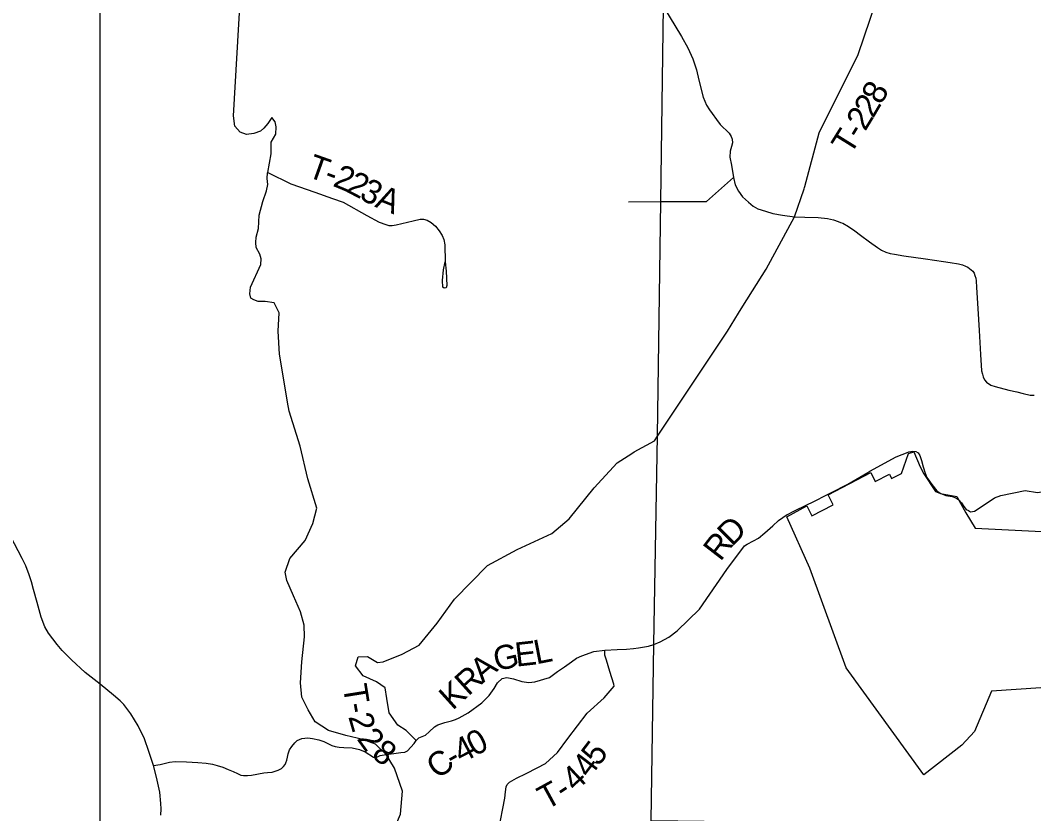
# Model space of a CAD drawing. Extents: x 2402298 to 2498138, y 789485 to 950881.
# Drawn here: x 2447192 to 2459820, y 871864 to 881754 of the extents above; entities that cross this region are included whole.
import ezdxf

# ---------------------------------------------------------------- set-up
doc = ezdxf.new("R2010")
doc.units = 0
for name, color, linetype in [('GM_X_Corporation', 7, 'Continuous'), ('GM_X_County_Road', 7, 'Continuous'), ('GM_X_County_Road_Text', 7, 'Continuous'), ('GM_X_State_Route', 7, 'Continuous'), ('GM_X_Township', 7, 'Continuous'), ('GM_X_Township_Road', 7, 'Continuous'), ('GM_X_Township_Road_Text', 7, 'Continuous'), ('SH_Text', 7, 'Continuous')]:
    doc.layers.add(name, color=color, linetype=linetype)

msp = doc.modelspace()

# ---------------------------------------------------------------- linework, layer by layer
at = {"layer": 'GM_X_Corporation'}
msp.add_lwpolyline([(2459910, 873433), (2459295, 873391), (2459082, 872888), (2458923, 872718), (2458450, 872349), (2457481, 873684), (2457030, 874924), (2456744, 875567), (2456993, 875700), (2457053, 875577), (2457321, 875713), (2457258, 875841), (2457789, 876118), (2457844, 876007), (2458022, 876097), (2458049, 876042), (2458172, 876104), (2458258, 876353), (2458325, 876376), (2458405, 876188), (2458451, 876100), (2458595, 875879), (2458657, 875856), (2458863, 875820), (2458972, 875616), (2459092, 875424), (2460004, 875376)], dxfattribs=at)
at = {"layer": 'GM_X_County_Road'}
for points in [[(2459300, 875783), (2459330, 875803), (2459408, 875832), (2459714, 875892), (2459866, 875867), (2460079, 875905), (2460148, 875978), (2460193, 876060), (2460432, 876476), (2460593, 876723), (2460629, 876769), (2460667, 876804), (2460721, 876846), (2460769, 876871)], [(2458257, 876372), (2458262, 876374), (2458312, 876385), (2458350, 876380), (2458379, 876363), (2458401, 876328), (2458421, 876267), (2458442, 876189), (2458467, 876110), (2458489, 876057), (2458522, 876010)], [(2457753, 876119), (2457779, 876135), (2458106, 876311), (2458257, 876372)], [(2457301, 875869), (2457504, 875972), (2457753, 876119)], [(2458522, 876010), (2458531, 875998), (2458566, 875948), (2458614, 875891), (2458661, 875855), (2458725, 875831), (2458804, 875819), (2458850, 875803), (2458885, 875778), (2458920, 875740), (2458948, 875695), (2458980, 875658), (2459005, 875642), (2459034, 875629), (2459082, 875637), (2459300, 875783)], [(2456750, 875595), (2456831, 875635), (2456994, 875714), (2457072, 875753)], [(2457072, 875753), (2457250, 875843), (2457301, 875869)], [(2454831, 873922), (2454894, 873932), (2455020, 873955), (2455088, 873975), (2455166, 874007), (2455273, 874066), (2455376, 874145), (2455656, 874415), (2455995, 874910), (2456216, 875202), (2456248, 875225), (2456330, 875264), (2456392, 875300), (2456468, 875364), (2456571, 875451), (2456641, 875518), (2456746, 875593), (2456750, 875595)], [(2448850, 872464), (2448935, 872480), (2449052, 872508), (2449121, 872514), (2449262, 872512), (2449404, 872502), (2449510, 872493), (2449589, 872481), (2449647, 872467), (2449717, 872445), (2449781, 872417), (2449843, 872389), (2449899, 872364), (2449942, 872346), (2449972, 872342), (2450024, 872339), (2450072, 872346), (2450228, 872374), (2450274, 872379), (2450331, 872384), (2450369, 872394), (2450407, 872408), (2450446, 872429), (2450473, 872453), (2450491, 872478), (2450500, 872500), (2450514, 872534), (2450522, 872569), (2450530, 872610), (2450547, 872663), (2450574, 872704), (2450614, 872747), (2450643, 872777), (2450701, 872804), (2450775, 872810), (2450835, 872802), (2450913, 872784), (2450976, 872763), (2451040, 872733), (2451075, 872713), (2451115, 872701), (2451166, 872694), (2451225, 872689), (2451329, 872687), (2451417, 872667), (2451490, 872638), (2451592, 872571), (2451627, 872566), (2451677, 872589), (2451751, 872603), (2451846, 872616), (2451933, 872626), (2451982, 872633), (2452017, 872649), (2452098, 872738), (2452126, 872778), (2452157, 872811), (2452243, 872845), (2452286, 872884), (2452355, 872946), (2452394, 872972), (2452480, 873002), (2452565, 873024), (2452613, 873039), (2452662, 873060), (2452771, 873123), (2452945, 873245), (2453034, 873339), (2453097, 873424), (2453137, 873497), (2453197, 873549), (2453255, 873563), (2453338, 873544), (2453443, 873512), (2453529, 873500), (2453602, 873507), (2453787, 873562), (2453885, 873636), (2453972, 873694), (2454061, 873758), (2454122, 873802), (2454187, 873833), (2454339, 873886), (2454474, 873903), (2454629, 873910), (2454744, 873917), (2454831, 873922)]]:
    msp.add_lwpolyline(points, dxfattribs=at)
at = {"layer": 'GM_X_State_Route'}
for points in [[(2455208, 881922), (2455429, 881553), (2455511, 881409), (2455574, 881273), (2455619, 881136), (2455645, 881007), (2455701, 880795), (2455744, 880695), (2455780, 880637), (2455811, 880592), (2455866, 880516), (2455914, 880453), (2456025, 880347), (2456050, 880306), (2456063, 880270), (2456065, 880228), (2456053, 880181), (2456036, 880121), (2456032, 880046), (2456053, 879946), (2456078, 879794), (2456100, 879702), (2456140, 879623), (2456191, 879555), (2456265, 879487), (2456324, 879438), (2456380, 879403), (2456476, 879373), (2456570, 879347), (2456689, 879324), (2456841, 879305), (2456969, 879301), (2457134, 879294), (2457252, 879282), (2457323, 879266), (2457382, 879247), (2457413, 879234)], [(2457413, 879234), (2457440, 879224), (2457513, 879183), (2457589, 879131), (2457662, 879076), (2457775, 878993), (2457872, 878922), (2457923, 878888), (2457977, 878864), (2458029, 878847), (2458084, 878837), (2458201, 878819), (2458471, 878779), (2458697, 878747), (2458780, 878736), (2458883, 878717), (2458933, 878704), (2458969, 878690), (2458997, 878676), (2459021, 878660), (2459039, 878645), (2459059, 878625), (2459076, 878601), (2459087, 878574), (2459098, 878539), (2459102, 878506), (2459108, 878423), (2459122, 878160), (2459139, 877889), (2459158, 877590), (2459170, 877386), (2459180, 877343), (2459191, 877308), (2459207, 877273), (2459233, 877242), (2459285, 877208), (2459338, 877188), (2459509, 877145), (2459611, 877122), (2459690, 877104), (2459775, 877080), (2459825, 877080)], [(2448850, 872464), (2448794, 872642), (2448738, 872797), (2448659, 872961), (2448571, 873108), (2448481, 873227), (2448435, 873272), (2448355, 873343), (2448187, 873479), (2447999, 873626), (2447832, 873783), (2447712, 873901), (2447650, 873975), (2447597, 874043), (2447545, 874113), (2447499, 874193), (2447452, 874313), (2447402, 874498), (2447358, 874661), (2447332, 874753), (2447303, 874840), (2447263, 874953), (2447215, 875045), (2447071, 875324)], [(2448942, 871847), (2448946, 871925), (2448943, 871990), (2448930, 872133), (2448888, 872322), (2448850, 872464)]]:
    msp.add_lwpolyline(points, dxfattribs=at)
at = {"layer": 'GM_X_Township'}
msp.add_lwpolyline([(2460401, 871709), (2459688, 871718), (2455055, 871774), (2455087, 873978), (2455132, 876575), (2455173, 879496), (2455207, 881924), (2455264, 885930), (2455318, 889770), (2455396, 895324), (2455493, 902184), (2455511, 903524), (2455798, 903521), (2455910, 903520), (2460796, 903505)], dxfattribs=at)
at = {"layer": 'GM_X_Township_Road'}
for points in [[(2456969, 879683), (2457147, 880350), (2457633, 881329), (2458235, 883104), (2458282, 883194)], [(2450274, 879851), (2450275, 879857), (2450297, 879973), (2450320, 880088), (2450317, 880236), (2450375, 880333), (2450381, 880425), (2450369, 880489), (2450326, 880544), (2450278, 880469), (2450227, 880408), (2450186, 880371), (2450100, 880341), (2450010, 880331), (2449930, 880359), (2449864, 880434), (2449849, 880564), (2449938, 882067), (2449934, 882475), (2449941, 882537), (2449977, 882593), (2450053, 882672), (2450207, 882812)], [(2450523, 876996), (2450502, 877123), (2450423, 877592), (2450405, 877878), (2450417, 878109), (2450356, 878231), (2450242, 878247), (2450155, 878247), (2450102, 878269), (2450064, 878290), (2450051, 878346), (2450061, 878429), (2450191, 878711), (2450193, 878780), (2450175, 878838), (2450131, 878922), (2450129, 878985), (2450132, 879049), (2450160, 879158), (2450165, 879240), (2450168, 879326), (2450216, 879494), (2450259, 879628), (2450275, 879707), (2450267, 879783), (2450274, 879851)], [(2450275, 879857), (2450562, 879717), (2450864, 879610), (2451082, 879532), (2451214, 879486), (2451511, 879321), (2451664, 879237), (2451747, 879209), (2451784, 879198), (2451824, 879198), (2451875, 879206), (2451947, 879223), (2452088, 879255), (2452173, 879273), (2452215, 879275), (2452262, 879263), (2452313, 879233), (2452366, 879187), (2452412, 879128), (2452450, 879071), (2452468, 879021), (2452484, 878955), (2452488, 878742), (2452497, 878627), (2452508, 878448), (2452499, 878419), (2452473, 878413), (2452459, 878426), (2452453, 878510), (2452464, 878642), (2452488, 878742)], [(2455208, 879494), (2455743, 879494), (2456078, 879794)], [(2456841, 879305), (2456960, 879655), (2456965, 879668), (2456969, 879683)], [(2454769, 879493), (2455174, 879494), (2455197, 879494), (2455208, 879494)], [(2456141, 878103), (2456197, 878192), (2456484, 878653), (2456841, 879305)], [(2454812, 876356), (2454840, 876374), (2455093, 876511), (2455133, 876572), (2456003, 877881), (2456141, 878103)], [(2451751, 872603), (2451619, 872731), (2451461, 872788), (2451248, 872839), (2451032, 872903), (2450868, 873011), (2450779, 873160), (2450701, 873316), (2450685, 873498), (2450700, 873759), (2450733, 874070), (2450728, 874216), (2450684, 874381), (2450598, 874582), (2450514, 874772), (2450494, 874876), (2450552, 875045), (2450743, 875272), (2450837, 875480), (2450889, 875672), (2450775, 876038), (2450680, 876444), (2450543, 876884), (2450523, 876996)], [(2451759, 873302), (2451740, 873432), (2451631, 873507), (2451464, 873585), (2451370, 873706), (2451401, 873818), (2451517, 873824), (2451644, 873751), (2451712, 873756), (2451951, 873853), (2452164, 873965), (2452387, 874238), (2452604, 874537), (2453014, 874958), (2453384, 875158), (2453814, 875359), (2454032, 875542), (2454342, 875928), (2454631, 876240), (2454812, 876356)], [(2453069, 871307), (2453049, 871410), (2453054, 871450), (2453151, 871650), (2453230, 872058), (2453239, 872138), (2453245, 872198), (2453260, 872228), (2453289, 872257), (2453377, 872307), (2453496, 872366), (2453631, 872437), (2453738, 872491), (2453885, 872628), (2454013, 872804), (2454255, 873117), (2454466, 873308), (2454594, 873454), (2454586, 873481), (2454537, 873636), (2454495, 873779), (2454475, 873841), (2454474, 873903)], [(2452126, 872778), (2452002, 872902), (2451897, 872967), (2451790, 873121), (2451759, 873302)], [(2452305, 869383), (2452306, 869405), (2452313, 869536), (2451886, 869803), (2451810, 870076), (2451806, 870242), (2451770, 870525), (2451544, 870697), (2451337, 870909), (2451316, 871078), (2451457, 871228), (2451565, 871305), (2451636, 871356), (2451825, 871614), (2451930, 871861), (2451953, 872146), (2451855, 872432), (2451751, 872603)]]:
    msp.add_lwpolyline(points, dxfattribs=at)
at = {"layer": 'SH_Text'}
msp.add_lwpolyline([(2448187, 889729), (2496836, 889729), (2496836, 859271), (2448187, 859271)], close=True, dxfattribs=at)

# ---------------------------------------------------------------- texts
at = {"layer": 'GM_X_County_Road_Text'}
for s, rotation, p in [('D', 44.9794, (2456060, 875187)), ('R', 52.3362, (2455916, 875000)), ('E', 6.4377, (2453372, 873697)), ('L', 10.9737, (2453621, 873726)), ('G', 12.8797, (2453124, 873639)), ('A', 40.1232, (2452955, 873486)), ('R', 41.9739, (2452774, 873323)), ('K', 41.9823, (2452578, 873146)), ('0', 27.8832, (2452852, 872574)), ('4', 27.752, (2452688, 872488)), ('C', 36.9035, (2452394, 872286)), ('-', 29.3799, (2452583, 872428))]:
    msp.add_text(s, height=300, rotation=rotation, dxfattribs=at).set_placement(p)
at = {"layer": 'GM_X_Township_Road_Text'}
for s, rotation, p in [('8', 60.8225, (2457917, 880690)), ('2', 59.253, (2457818, 880523)), ('2', 58.5651, (2457720, 880362)), ('T', 58.1741, (2457536, 880065)), ('-', 58.2489, (2457654, 880256)), ('T', 340.4171, (2450752, 879809)), ('2', 337.2941, (2451075, 879693)), ('-', 339.5874, (2450963, 879734)), ('2', 332.4691, (2451240, 879624)), ('3', 330.9975, (2451402, 879540)), ('A', 338.1519, (2451600, 879432)), ('T', 279.1023, (2451210, 873457)), ('-', 280.4116, (2451247, 873228)), ('2', 286.2071, (2451277, 873075)), ('2', 305.8587, (2451378, 872797)), ('8', 323.1255, (2451555, 872577)), ('5', 52.7065, (2454395, 872444)), ('4', 52.8517, (2454283, 872297)), ('4', 42.9457, (2454110, 872129)), ('T', 28.6891, (2453745, 871906)), ('-', 33.4929, (2453965, 872027))]:
    msp.add_text(s, height=300, rotation=rotation, dxfattribs=at).set_placement(p)

doc.saveas('drawing.dxf')
